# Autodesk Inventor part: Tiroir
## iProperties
Author: Flavien MARTY
Shininess: 100.0
PropertySet Name: _Private Model Information
Created: 2001-10
Part Number: Tiroir
Material: Par défaut
Document SubType Name: Modélisation
Designer: Flavien MARTY
Control State: 0
Master: False
Checked Out: False
PropertySet Name: Design Tracking Control
Density: 0.0
Volumn: 0.0
Area: 0.0
PropertySet Name: Model Information
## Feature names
1. Base1
